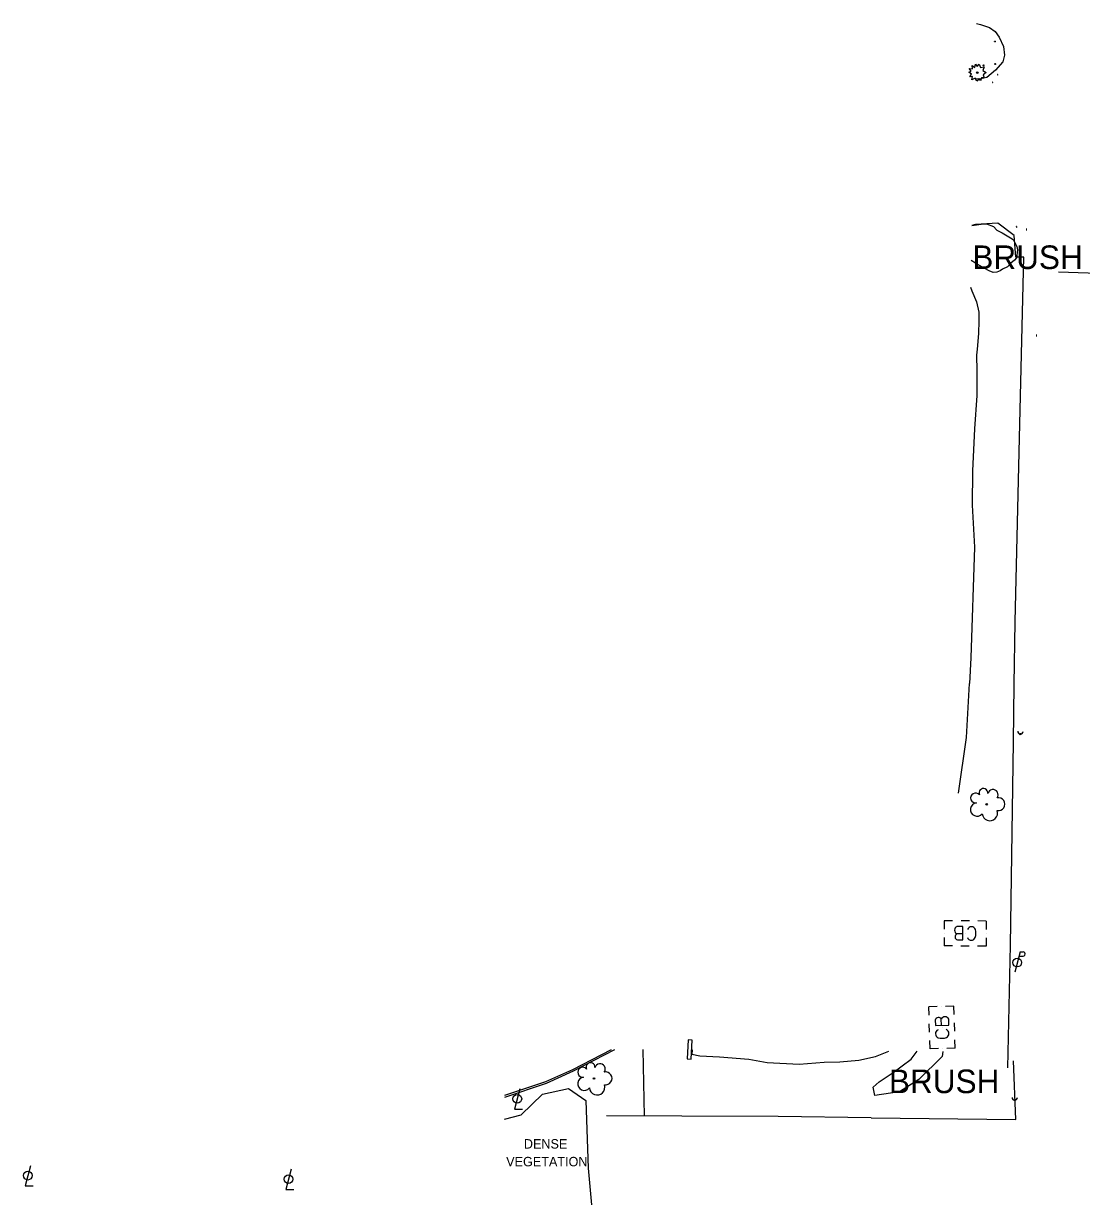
# Model space of a CAD drawing. Extents: x 2129547 to 2134906, y 657330 to 659734.
# Drawn here: x 2132170.9 to 2132484.8, y 659187.6 to 659535.8 of the extents above; entities that cross this region are included whole.
import ezdxf

# ---------------------------------------------------------------- set-up
doc = ezdxf.new("R2010")
doc.units = 0
for name, color, linetype in [('Default', 7, 'Continuous'), ('DR_X_Cells', 7, 'Continuous'), ('DR_X_Culvert', 7, 'Continuous'), ('HY_X_Water_Edge', 7, 'Continuous'), ('LT_X_Poles', 7, 'Continuous'), ('PV_X_Curb', 7, 'Continuous'), ('PV_X_Parking_Lot', 7, 'Continuous'), ('RD_X_Cells', 7, 'Continuous'), ('RD_X_Fence', 7, 'Continuous'), ('SN_X_Cantilever_Overhead', 7, 'Continuous'), ('UT_X_Electric_Cells', 7, 'Continuous'), ('UT_X_Misc_Cells', 7, 'Continuous'), ('UT_X_Unknown_Cells', 7, 'Continuous'), ('VG_X_Cells', 7, 'Continuous'), ('VG_X_Flower_Bed', 7, 'Continuous'), ('VG_X_Shrub_Line_Lt', 7, 'Continuous'), ('VG_X_Text', 7, 'Continuous'), ('VG_X_Tree_Line_Lt', 7, 'Continuous')]:
    doc.layers.add(name, color=color, linetype=linetype)

# ---------------------------------------------------------------- blocks, each defined once
blk = doc.blocks.new('DM')
at = {"layer": 'UT_X_Misc_Cells'}
blk.add_circle((0, 0), 0.00254, dxfattribs=at)
blk.add_arc((0.01016, 0), 0.01016, 90, 270, dxfattribs=at)
blk = doc.blocks.new('LPOLE')
at = {"layer": 'LT_X_Poles'}
blk.add_lwpolyline([(0.01, 0.0375), (-0.01, -0.0385), (0.02, -0.0385)], dxfattribs=at)
blk.add_circle((0, 0), 0.0165, dxfattribs=at)
blk = doc.blocks.new('PP')
at = {"layer": 'UT_X_Electric_Cells'}
for p, q in [((0.0109, 0.0406), (-0.0095, -0.0356)), ((0.0065, 0.0244), (0.0217, 0.0244)), ((0.0109, 0.0406), (0.0217, 0.0406))]:
    blk.add_line(p, q, dxfattribs=at)
blk.add_circle((0, 0), 0.0165, dxfattribs=at)
blk.add_arc((0.0218, 0.0325), 0.0081, 268.8767, 91.1233, dxfattribs=at)
blk = doc.blocks.new('TREE')
at = {"layer": 'VG_X_Cells'}
blk.add_circle((0, 0), 0.00305, dxfattribs=at)
for centre, radius, start, end in [((-0.0125, 0.0428), 0.0167, 354.0047, 205.9741), ((0.0232, 0.0359), 0.0197, 323.83, 165.0376), ((-0.0362, -0.0197), 0.0251, 96.1722, 320.5737), ((-0.042, 0.0237), 0.0187, 39.0625, 279.5412), ((0.0439, 0.0005), 0.0243, 259.1453, 101.4596), ((0.012, -0.0331), 0.029, 184.9476, 19.4572)]:
    blk.add_arc(centre, radius, start, end, dxfattribs=at)
blk = doc.blocks.new('POINT_DISPLAY')
at = {"layer": 'Default'}
blk.add_line((0, 0), (0, 0), dxfattribs=at)
blk = doc.blocks.new('GCB-X')
at = {"layer": 'Default'}
for p, q in [((-0.0317, 0.019), (-0.019, 0.019)), ((-0.0317, 0.0063), (-0.0317, 0.019)), ((-0.0063, 0.019), (0.0063, 0.019)), ((0.019, 0.019), (0.0317, 0.019)), ((0.0317, 0.0063), (0.0317, 0.019)), ((0.0034, 0.0007), (0.0124, 0.0007)), ((-0.0317, -0.019), (-0.0317, -0.0063)), ((0.0317, -0.019), (0.0317, -0.0063)), ((-0.0317, -0.019), (-0.019, -0.019)), ((-0.0063, -0.019), (0.0063, -0.019)), ((0.019, -0.019), (0.0317, -0.019))]:
    blk.add_line(p, q, dxfattribs=at)
blk.add_lwpolyline([(0.0116, 0.0099), (0.0034, 0.0099), (0.0034, -0.0104), (0.0124, -0.0104)], dxfattribs=at)
for centre, radius, start, end in [((0.0071, 0), 0.0233, 164.8107, 195.1893), ((-0.0094, 0.0037), 0.00645, 21.5603, 158.4397), ((0.0101, 0.0051), 0.00501, 296.8207, 73.0013), ((0.0101, -0.0049), 0.00597, 292.0547, 67.9453), ((-0.0094, -0.0037), 0.00645, 201.5603, 338.4397)]:
    blk.add_arc(centre, radius, start, end, dxfattribs=at)
for p in [(0, 0.019), (0, 0.019), (-0.0317, 0), (0, 0), (0, 0), (0, 0), (0.0317, 0), (0, -0.019), (0, -0.019)]:
    blk.add_blockref('POINT_DISPLAY', p, dxfattribs=at)

msp = doc.modelspace()

# ---------------------------------------------------------------- linework, layer by layer
at = {"layer": 'DR_X_Culvert'}
msp.add_lwpolyline([(2132368.05, 659234.11), (2132367.81, 659228.46), (2132369.01, 659228.41), (2132369.25, 659234.06)], close=True, dxfattribs=at)
at = {"layer": 'HY_X_Water_Edge'}
for points in [[(2132451.81, 659457.47), (2132452.26, 659456.38), (2132453.68, 659453.16), (2132454.29, 659450.11), (2132454.37, 659447.51), (2132454.22, 659443.78), (2132453.82, 659439.05), (2132453.62, 659437.32), (2132453.72, 659432.66), (2132453.72, 659425.33), (2132453.08, 659415.45), (2132452.49, 659403.02), (2132452.31, 659392.83), (2132453.08, 659380.3), (2132451.99, 659347.47), (2132451.56, 659339.83)], [(2132448.32, 659307.31), (2132450.68, 659323.87), (2132451.56, 659339.83)], [(2132369.26, 659231.13), (2132369.19, 659229.91), (2132371.58, 659229.41), (2132377.42, 659229.08), (2132386.11, 659228.34), (2132391.57, 659227.38), (2132401.05, 659226.9), (2132408.47, 659227.52), (2132413.1, 659227.62), (2132418.77, 659228.05), (2132423.62, 659229.22), (2132427.59, 659230.77)]]:
    msp.add_lwpolyline(points, dxfattribs=at)
at = {"layer": 'PV_X_Curb'}
msp.add_lwpolyline([(2132313.71, 659217.14), (2132326.03, 659221.29), (2132334.1, 659224.9), (2132346.37, 659231.26)], dxfattribs=at)
at = {"layer": 'PV_X_Parking_Lot'}
msp.add_lwpolyline([(2132313.71, 659217.68), (2132325.85, 659221.75), (2132333.88, 659225.35), (2132345.3, 659231.27)], dxfattribs=at)
at = {"layer": 'RD_X_Cells'}
for points in [[(2132459.83, 659520.48), (2132459.9, 659520.45), (2132459.96, 659520.48), (2132459.96, 659520.56), (2132459.9, 659520.6), (2132459.83, 659520.56), (2132459.83, 659520.48)], [(2132458.38, 659518.23), (2132458.44, 659518.19), (2132458.51, 659518.23), (2132458.51, 659518.31), (2132458.44, 659518.34), (2132458.38, 659518.31), (2132458.38, 659518.23)]]:
    msp.add_lwpolyline(points, dxfattribs=at)
at = {"layer": 'RD_X_Fence'}
for p, q in [((2132464.82, 659339.56), (2132465.1, 659358.13)), ((2132355.09, 659211.5), (2132354.75, 659231.21))]:
    msp.add_line(p, q, dxfattribs=at)
for points in [[(2132465.1, 659358.13), (2132466.49, 659416.97), (2132467.66, 659466.44), (2132465.3, 659466.43), (2132464.8, 659472.84), (2132459.98, 659476.51), (2132453.34, 659476.06), (2132452.25, 659475.8)], [(2132462.88, 659225.78), (2132463.67, 659262.25), (2132464.57, 659322.42), (2132464.82, 659339.56)], [(2132422.38, 659210.94), (2132465.33, 659210.49), (2132464.64, 659227.91)], [(2132422.38, 659210.94), (2132394.76, 659211.39), (2132366.17, 659211.47), (2132343.86, 659211.52)]]:
    msp.add_lwpolyline(points, dxfattribs=at)
at = {"layer": 'SN_X_Cantilever_Overhead'}
msp.add_line((2132477.95, 659462.06), (2132498.68, 659461.4), dxfattribs=at)
at = {"layer": 'UT_X_Unknown_Cells'}
for p, q in [((2132465.57, 659475.46), (2132465.51, 659475.46)), ((2132465.51, 659475.4), (2132465.51, 659475.33)), ((2132465.54, 659475.43), (2132465.54, 659475.49)), ((2132465.57, 659475.4), (2132465.57, 659475.33)), ((2132468.43, 659474.64), (2132468.43, 659474.58)), ((2132468.48, 659474.64), (2132468.48, 659474.58)), ((2132471.38, 659443.19), (2132471.38, 659443.13)), ((2132471.43, 659443.19), (2132471.43, 659443.13))]:
    msp.add_line(p, q, dxfattribs=at)
for points in [[(2132468.5, 659474.56), (2132468.5, 659474.64), (2132468.53, 659474.56), (2132468.56, 659474.64), (2132468.56, 659474.56)], [(2132471.46, 659443.11), (2132471.46, 659443.19), (2132471.49, 659443.11), (2132471.52, 659443.19), (2132471.52, 659443.11)]]:
    msp.add_lwpolyline(points, dxfattribs=at)
for centre, radius, start, end in [((2132465.54, 659475.36), 0.07, 150.0184, 209.9816), ((2132465.54, 659475.36), 0.07, 60.0184, 120.0157), ((2132465.54, 659475.34), 0.03, 205.1924, 334.8076), ((2132465.54, 659475.36), 0.07, 239.9843, 299.9816), ((2132465.54, 659475.36), 0.07, 330.0184, 29.9816), ((2132468.49, 659474.6), 0.1, 160.0169, 200.0392), ((2132468.49, 659474.6), 0.1, 100.0806, 140.0721), ((2132468.49, 659474.6), 0.1, 220.0577, 260.0473), ((2132468.45, 659474.59), 0.0279, 205.1924, 334.8076), ((2132468.49, 659474.6), 0.1, 40.0577, 80.1061), ((2132468.49, 659474.6), 0.1, 280.0114, 320.0264), ((2132468.49, 659474.6), 0.1, 340.0169, 20.0392), ((2132471.45, 659443.15), 0.1, 160.0169, 200.0392), ((2132471.45, 659443.15), 0.1, 100.0806, 140.0721), ((2132471.45, 659443.15), 0.1, 220.0577, 260.0473), ((2132471.41, 659443.14), 0.0279, 205.1924, 334.8076), ((2132471.45, 659443.15), 0.1, 40.0577, 80.1061), ((2132471.45, 659443.15), 0.1, 280.0114, 320.0264), ((2132471.45, 659443.15), 0.1, 340.0169, 20.0392)]:
    msp.add_arc(centre, radius, start, end, dxfattribs=at)
at = {"layer": 'VG_X_Cells'}
for points in [[(2132459.1, 659530.5), (2132459.13, 659530.54), (2132459.15, 659530.48), (2132459.2, 659530.49), (2132459.18, 659530.44), (2132459.23, 659530.41), (2132459.19, 659530.37), (2132459.2, 659530.33), (2132459.16, 659530.33), (2132459.15, 659530.29), (2132459.13, 659530.32), (2132459.09, 659530.28), (2132459.07, 659530.32), (2132459.02, 659530.3), (2132459.03, 659530.35), (2132458.99, 659530.35), (2132459.01, 659530.39), (2132458.97, 659530.41), (2132459.01, 659530.43), (2132458.98, 659530.47), (2132459.03, 659530.46), (2132459.03, 659530.51), (2132459.06, 659530.49), (2132459.07, 659530.53), (2132459.1, 659530.5)], [(2132453.78, 659522.97), (2132454.38, 659523.71), (2132454.8, 659522.65), (2132455.89, 659522.83), (2132455.55, 659521.82), (2132456.5, 659521.23), (2132455.64, 659520.49), (2132455.89, 659519.58), (2132455.14, 659519.65), (2132454.81, 659518.73), (2132454.38, 659519.43), (2132453.7, 659518.61), (2132453.28, 659519.5), (2132452.26, 659519.07), (2132452.45, 659520.01), (2132451.64, 659519.92), (2132452.11, 659520.71), (2132451.34, 659521.28), (2132452.08, 659521.55), (2132451.47, 659522.35), (2132452.4, 659522.24), (2132452.37, 659523.28), (2132453.13, 659522.71), (2132453.33, 659523.69), (2132453.78, 659522.97)], [(2132455.73, 659523.44), (2132455.76, 659523.47), (2132455.78, 659523.42), (2132455.83, 659523.43), (2132455.82, 659523.38), (2132455.86, 659523.35), (2132455.82, 659523.31), (2132455.83, 659523.27), (2132455.8, 659523.27), (2132455.78, 659523.23), (2132455.76, 659523.26), (2132455.72, 659523.22), (2132455.7, 659523.26), (2132455.65, 659523.24), (2132455.66, 659523.29), (2132455.62, 659523.28), (2132455.65, 659523.32), (2132455.61, 659523.35), (2132455.64, 659523.37), (2132455.61, 659523.41), (2132455.66, 659523.4), (2132455.66, 659523.45), (2132455.7, 659523.42), (2132455.71, 659523.47), (2132455.73, 659523.44)], [(2132459.18, 659523.8), (2132459.21, 659523.84), (2132459.23, 659523.79), (2132459.28, 659523.8), (2132459.26, 659523.74), (2132459.31, 659523.72), (2132459.27, 659523.68), (2132459.28, 659523.63), (2132459.24, 659523.64), (2132459.23, 659523.59), (2132459.21, 659523.62), (2132459.17, 659523.58), (2132459.15, 659523.63), (2132459.1, 659523.61), (2132459.11, 659523.65), (2132459.07, 659523.65), (2132459.09, 659523.69), (2132459.05, 659523.72), (2132459.09, 659523.73), (2132459.06, 659523.77), (2132459.11, 659523.77), (2132459.11, 659523.82), (2132459.14, 659523.79), (2132459.15, 659523.84), (2132459.18, 659523.8)]]:
    msp.add_lwpolyline(points, dxfattribs=at)
for centre, radius in [((2132459.1, 659530.41), 0.0115), ((2132455.73, 659523.35), 0.0115), ((2132459.18, 659523.71), 0.0115), ((2132453.86, 659521.16), 0.23)]:
    msp.add_circle(centre, radius, dxfattribs=at)
at = {"layer": 'VG_X_Flower_Bed'}
msp.add_lwpolyline([(2132453.68, 659535.75), (2132454.85, 659535.49), (2132457.49, 659534.56), (2132459.12, 659533.41), (2132460.39, 659531.65), (2132461.68, 659528.89), (2132461.92, 659526.39), (2132461.42, 659524.32), (2132459.3, 659521.85), (2132456.7, 659519.72), (2132454.96, 659519.36), (2132453.56, 659519.22), (2132453.29, 659519.25)], dxfattribs=at)
at = {"layer": 'VG_X_Shrub_Line_Lt'}
for points in [[(2132452.25, 659475.81), (2132455.02, 659476.18), (2132456.61, 659476.3), (2132458.69, 659475.46), (2132459.64, 659474.43), (2132461.22, 659473.58), (2132463.68, 659472.12), (2132464.49, 659471.65), (2132465.63, 659469.53), (2132465.84, 659468.55), (2132465.45, 659466.22), (2132464.86, 659465.54), (2132463.8, 659464.64), (2132462.78, 659463.49), (2132461.38, 659462.82), (2132460.68, 659462.32), (2132459.64, 659461.95), (2132458.54, 659461.85), (2132457.43, 659462.33), (2132455.91, 659463.15), (2132453.29, 659464.6), (2132452, 659465.45)], [(2132443.61, 659230.68), (2132443.46, 659229.14), (2132436.49, 659222.34), (2132430.75, 659218.65), (2132423.51, 659217.56), (2132423.02, 659220.1), (2132424.72, 659221.61), (2132428.86, 659224.4)], [(2132428.86, 659224.4), (2132434.23, 659228.41), (2132436, 659230.72)]]:
    msp.add_lwpolyline(points, dxfattribs=at)
at = {"layer": 'VG_X_Tree_Line_Lt'}
msp.add_lwpolyline([(2132313.6, 659210.57), (2132318.52, 659211.91), (2132324.84, 659217.98), (2132332.62, 659219.63), (2132337.69, 659216.13), (2132338.46, 659196), (2132339.64, 659182.93)], dxfattribs=at)

# ---------------------------------------------------------------- block references
at = {"layer": 'DR_X_Cells', "xscale": 196.85}
for p, yscale, rotation in [((2132450.26, 659265.69), 196.85000000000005, 179.53836091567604), ((2132443.4, 659237.78), 196.85000000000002, 91.69590070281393)]:
    msp.add_blockref('GCB-X', p, dxfattribs=dict(at, yscale=yscale, rotation=rotation))
at = {"layer": 'LT_X_Poles', "xscale": 78.74000000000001, "yscale": 78.74000000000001}
for p in [(2132317.39, 659216.6), (2132172.18, 659193.82), (2132249.49, 659192.76)]:
    msp.add_blockref('LPOLE', p, dxfattribs=at)
at = {"layer": 'UT_X_Electric_Cells', "xscale": 78.74000000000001, "yscale": 78.74000000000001}
msp.add_blockref('PP', (2132465.73, 659257.04), dxfattribs=at)
at = {"layer": 'UT_X_Misc_Cells'}
for p, xscale, yscale, rotation in [((2132466.6, 659324.87), 78.74000000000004, 78.74000000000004, 85.63137159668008), ((2132464.97, 659216.22), 78.74000000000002, 78.74000000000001, 89.6567887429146)]:
    msp.add_blockref('DM', p, dxfattribs=dict(at, xscale=xscale, yscale=yscale, rotation=rotation))
at = {"layer": 'UT_X_Unknown_Cells', "xscale": 3.9370000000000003, "yscale": 3.9370000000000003}
for p in [(2132465.54, 659475.36), (2132468.49, 659474.6), (2132471.45, 659443.15)]:
    msp.add_blockref('POINT_DISPLAY', p, dxfattribs=at)
at = {"layer": 'VG_X_Cells', "xscale": 78.74000000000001, "yscale": 78.74000000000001}
for p in [(2132456.66, 659304.01), (2132340.12, 659222.64)]:
    msp.add_blockref('TREE', p, dxfattribs=at)

# ---------------------------------------------------------------- texts
at = {"layer": 'VG_X_Text'}
for s, height, p in [('BRUSH', 7, (2132452.39, 659462.87)), ('BRUSH', 7, (2132427.66, 659218.3)), ('DENSE', 2.8, (2132319.34, 659201.85)), ('VEGETATION', 2.8, (2132314.09, 659196.58))]:
    msp.add_text(s, height=height, dxfattribs=at).set_placement(p)

doc.saveas('drawing.dxf')
